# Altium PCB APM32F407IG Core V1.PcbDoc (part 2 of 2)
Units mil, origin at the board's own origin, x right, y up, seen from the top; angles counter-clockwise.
Board outline 2360 x 2950 mil, 4 copper layers (Top Layer, Signal, GND, Bottom Layer); 55 components, 152 nets, 502 pads, 608 vias.
Unrouted connection lines stored in the file: 294.
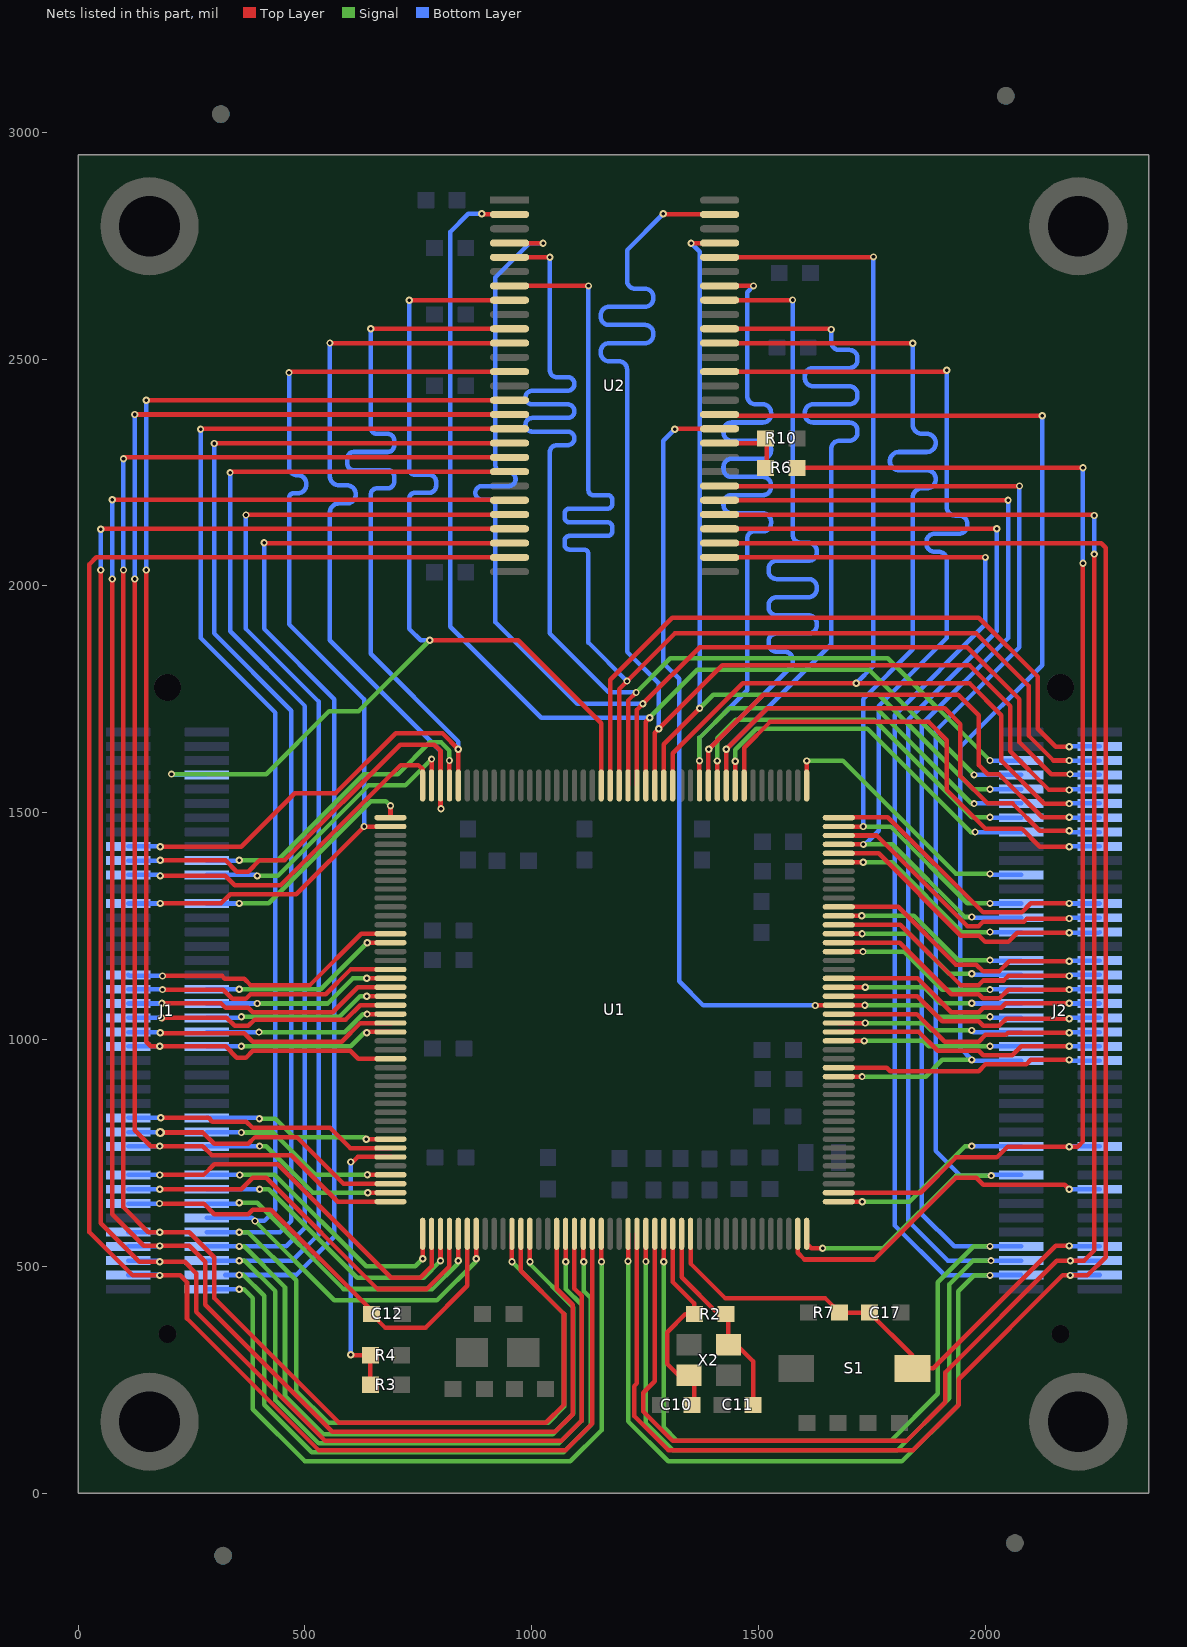
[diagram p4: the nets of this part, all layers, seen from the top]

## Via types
v1: diameter 16, hole 8, Top Layer to Bottom Layer, 452 vias
v2: diameter 24, hole 12, Top Layer to Bottom Layer, 149 vias
v3: diameter 20, hole 10, Top Layer to Bottom Layer, 7 vias

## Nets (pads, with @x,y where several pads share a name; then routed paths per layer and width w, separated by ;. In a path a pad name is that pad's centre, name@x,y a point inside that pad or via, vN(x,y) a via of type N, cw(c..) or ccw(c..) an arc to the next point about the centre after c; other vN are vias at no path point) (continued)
PD4_LCD_RD: J1.36 U1.146 | length 634.5
  Top Layer w10: v1(186.06,1140) 317.31,1140 323.31,1134 366,1134 380,1120 511.06,1120 624.21,1233.15 U1.146@688.58,1233.15
  Bottom Layer w10: J1.36@110.2,1142.31 112.5,1140 v1(186.06,1140)
PD5_LCD_WR: J1.37 U1.147 | length 447.7
  Top Layer w10: v1(637.6,1213.46) U1.147@688.58,1213.46
  Signal w10: v1(355,1110.81) 534.94,1110.81 v1(637.6,1213.46)
  Bottom Layer w10: J1.37@283.43,1110.81 v1(355,1110.81)
PD6_CTP_RST: J1.38 U1.150 | length 613.7
  Top Layer w10: v1(186.06,1110) 320,1110 340,1090 370,1090 380,1100 546.06,1100 600.47,1154.41 U1.150@688.58,1154.41
  Signal w10: v1@185.25,1110.81 v1(186.06,1110)
  Bottom Layer w10: J1.38@110.2,1110.81 v1@185.25,1110.81
PD7_CTP_SCL: J1.39 U1.151 | length 428.1
  Top Layer w10: v1(636.34,1134.72) U1.151@688.58,1134.72
  Signal w10: v1(395,1079.31) 550.38,1079.31 605.79,1134.72 v1(636.34,1134.72)
  Bottom Layer w10: J1.39@283.43,1079.31 v1(395,1079.31)
PD8_SMC_D13: J2.17 U1.96 | length 1069.2
  Top Layer w10: U1.96@1468.11,1559.92 1468.11,1643.11 1525,1700 1875,1700 1915,1660 1915,1550 2000,1465 2080,1465 2120,1425 v1(2185,1425)
  Bottom Layer w10: v1(2185,1425) 2185.77,1425.77 J2.17@2251.93,1425.77
PD9_SMC_D14: J2.16 U1.97 | length 822.4
  Top Layer w10: U1.97@1448.43,1559.92 v1(1448.43,1613.43)
  Signal w10: v1(1448.43,1613.43) 1448.43,1638.43 1495,1685 1740,1685 1967.73,1457.27 v1(1977.27,1457.27)
  Bottom Layer w10: v1(1977.27,1457.27) J2.16@2078.7,1457.27
PD10_SDR_D10: J2.15 U1.98 U2.45 | length 2874.1
  Top Layer w10: U2.45@1414.05,2566.64 v1@1660,2566.64 ; U1.98@1428.74,1559.92 v1(1428.74,1640) 1518.74,1730 1910,1730 1945,1695 1945,1580 2004.74,1520.26 2059.74,1520.26 2120,1460 v1(2184.53,1460)
  Bottom Layer w10: v1(1428.74,1640) 1660,1871.26 1660,2302 cw(c1678,2302) 1678,2320 1699.92,2320 ccw(c1699.92,2338) 1717.92,2338 1717.92,2342 ccw(c1699.92,2342) 1699.92,2360 1620.08,2360 cw(c1620.08,2378) 1602.08,2378 1602.08,2382 cw(c1620.08,2382) 1620.08,2400 1699.92,2400 ccw(c1699.92,2418) 1717.92,2418 1717.92,2422 ccw(c1699.92,2422) 1699.92,2440 1620.08,2440 cw(c1620.08,2458) 1602.08,2458 1602.08,2462 cw(c1620.08,2462) 1620.08,2480 1699.92,2480 ccw(c1699.92,2498) 1717.92,2498 1717.92,2502 ccw(c1699.92,2502) 1699.92,2520 1678,2520 cw(c1678,2538) 1660,2538 v1(1660,2565) ; v1(2184.53,1460) 2187.27,1457.27 J2.15@2251.93,1457.27
PD11_ETH_RESET: J2.14 U1.99 | length 880.3
  Top Layer w10: U1.99@1409.06,1559.92 v1(1409.06,1614.06)
  Signal w10: v1(1409.06,1614.06) 1409.06,1664.06 1450,1705 1755,1705 1970,1490 v1(2010,1490)
  Bottom Layer w10: v1(2010,1490) 2011.24,1488.76 J2.14@2078.7,1488.76
PD12_SDR_D11: J2.13 U1.100 U2.47 | length 2925
  Top Layer w10: U1.100@1389.37,1559.92 1389.37,1639.37 v1(1390,1640) 1510,1760 1940,1760 1985,1715 1985,1605 2005,1585 2030,1585 2125,1490 v1(2185,1490) ; U2.47@1414.05,2629.63 v1@1575,2629.63
  Bottom Layer w10: v1(1390,1640) 1575,1825 1575,1837 ccw(c1557,1837) 1557,1855 1539.93,1855 cw(c1539.93,1873) 1521.93,1873 1521.93,1877 cw(c1539.93,1877) 1539.93,1895 1610.06,1895 ccw(c1610.06,1913) 1628.06,1913 1628.06,1917 ccw(c1610.06,1917) 1610.06,1935 1539.94,1935 cw(c1539.94,1953) 1521.94,1953 1521.94,1957 cw(c1539.94,1957) 1539.94,1975 1610.06,1975 ccw(c1610.06,1993) 1628.06,1993 1628.06,1997 ccw(c1610.06,1997) 1610.06,2015 1539.94,2015 cw(c1539.94,2033) 1521.94,2033 1521.94,2037 cw(c1539.94,2037) 1539.94,2055 1610.06,2055 ccw(c1610.06,2073) 1628.06,2073 1628.06,2077 ccw(c1610.06,2077) 1610.06,2095 1593,2095 cw(c1593,2113) 1575,2113 v1(1575,2630) ; v1(2185,1490) 2186.24,1488.76 J2.13@2251.93,1488.76
PD13_SDR_D12: J2.12 U1.101 U2.48 | length 2709.7
  Top Layer w10: U1.101@1369.69,1559.92 v1(1369.69,1614.69) ; U2.48@1414.05,2661.13 v1(1488.87,2661.13)
  Signal w10: v1(1369.69,1614.69) 1369.69,1664.69 1435,1730 1760,1730 1970,1520 v1(1975,1520)
  Bottom Layer w10: v1(1369.69,1614.69) 1369.69,1664.69 1475,1770 1475,2105 cw(c1490,2105) 1490,2120 1509.39,2120 ccw(c1509.39,2138) 1527.39,2138 1527.39,2142 ccw(c1509.39,2142) 1509.39,2160 1440.61,2160 cw(c1440.61,2178) 1422.61,2178 1422.61,2182 cw(c1440.61,2182) 1440.61,2200 1509.39,2200 ccw(c1509.39,2218) 1527.39,2218 1527.39,2222 ccw(c1509.39,2222) 1509.39,2240 1440.61,2240 cw(c1440.61,2258) 1422.61,2258 1422.61,2262 cw(c1440.61,2262) 1440.61,2280 1509.39,2280 ccw(c1509.39,2298) 1527.39,2298 1527.39,2302 ccw(c1509.39,2302) 1509.39,2320 1440.61,2320 cw(c1440.61,2338) 1422.61,2338 1422.61,2342 cw(c1440.61,2342) 1440.61,2360 1509.39,2360 ccw(c1509.39,2378) 1527.39,2378 1527.39,2382 ccw(c1509.39,2382) 1509.39,2400 1493,2400 cw(c1493,2418) 1475,2418 1475,2647.25 v1(1488.87,2661.13) ; v1(1975,1520) 1975.26,1520.26 J2.12@2078.7,1520.26
PD14_SDR_D13: J2.11 U1.104 U2.50 | length 2541.6
  Top Layer w10: U1.104@1310.63,1559.92 1310.63,1630.63 1465,1785 v1(1715,1785) 1965,1785 2035,1715 2035,1615 2130,1520 v1(2185,1520) ; U2.50@1414.05,2724.12 1754.12,2724.12 v1(1753.24,2725)
  Bottom Layer w10: v1(1715,1785) 1753.24,1823.24 v1(1753.24,2725) ; v1(2185,1520) 2185.26,1520.26 J2.11@2251.93,1520.26
PD15_SDR_D14: J2.10 U1.105 U2.51 | length 2107.3
  Top Layer w10: U1.105@1290.94,1559.92 1290.94,1650.94 v1(1370,1730) ; v1(1351.23,2755) 1350.61,2755.61 U2.51@1414.05,2755.61
  Signal w10: v1(1370,1730) 1400,1760 1765,1760 1973.25,1551.75 v1(2010,1551.75)
  Bottom Layer w10: v1(1351.23,2755) 1370,2736.23 v1(1370,1730) ; v1(2010,1551.75) J2.10@2078.7,1551.75
PDR_ON: R3.1 R4.2 U1.171 | length 625.6
  Top Layer w10: v1(601.06,305) 602.06,304 R4.2@644.16,304 R3.1@644.16,239 ; v1(601.06,730) 605.04,730 616.06,741.02 U1.171@688.58,741.02
  Bottom Layer w10: v1(601.06,305) v1(601.06,730)
PE0: J1.55 U1.169 | length 424.9
  Top Layer w10: v1(635,780) 635.39,780.39 U1.169@688.58,780.39
  Signal w10: v1(399.69,825) 435,825 475,785 630,785 v1(635,780)
  Bottom Layer w10: J1.55@283.43,827.34 397.34,827.34 v1(399.69,825)
PE1: J1.56 U1.170 | length 606
  Top Layer w10: v1(182.34,827.34) 287.66,827.34 296,819 371,819 385,805 555.71,805 600,760.71 U1.170@688.58,760.71
  Bottom Layer w10: J1.56@110.2,827.34 v1(182.34,827.34)
PE2_CTP_INT: J1.63 U1.1 | length 621.4
  Top Layer w10: v1(759.45,516.61) U1.1@759.45,571.73
  Signal w10: v1(356.36,701.36) 433.64,701.36 635,500 742.83,500 v1(759.45,516.61)
  Bottom Layer w10: J1.63@283.43,701.36 v1(356.36,701.36)
PE3_LCD_RST: J1.64 U1.2 | length 864.4
  Top Layer w10: v1(179.7,701.36) 276.36,701.36 300,725 440,725 690,475 754.13,475 779.13,500 U1.2@779.13,571.73
  Bottom Layer w10: J1.64@110.2,701.36 v1(179.7,701.36)
PE4_DCMI_D4: J1.65 U1.3 | length 671.1
  Top Layer w10: v1(798.82,512.24) U1.3@798.82,571.73
  Signal w10: v1(400,670) 420,670 615,475 761.57,475 v1(798.82,512.24)
  Bottom Layer w10: J1.65@283.43,669.86 399.86,669.86 v1(400,670)
PE5_DCMI_D6: J1.66 U1.4 | length 913.6
  Top Layer w10: v1(180,669.86) 359.86,669.86 385,695 415,695 660,450 768.5,450 818.5,500 U1.4@818.5,571.73
  Bottom Layer w10: J1.66@110.2,669.86 v1(180,669.86) v1@180.93,669.86
PE6_DCMI_D7: J1.67 U1.5 | length 722.4
  Top Layer w10: v1(838.19,512.13) U1.5@838.19,571.73
  Signal w10: v1(355,640) 395,640 585,450 781.06,450 838.19,507.13 v1(838.19,512.13)
  Bottom Layer w10: J1.67@283.43,638.37 353.37,638.37 v1(355,640)
PE7_SMC_D4: J2.41 U1.68 | length 609.6
  Top Layer w10: U1.68@1676.77,1095.35 1849.65,1095.35 1905,1040 1985,1040 1995,1030 2030,1030 2045.63,1045.63 v1(2185,1045.63)
  Bottom Layer w10: v1(2185,1045.63) 2187.18,1047.82 J2.41@2251.93,1047.82
PE8_SMC_D5: J2.40 U1.69 | length 416.7
  Top Layer w10: U1.69@1676.77,1115.04 v1(1734.96,1115.04)
  Signal w10: v1(1734.96,1115.04) 1864.96,1115.04 1900,1080 v1(1970,1080)
  Bottom Layer w10: v1(1970,1080) 1970.69,1079.31 J2.40@2078.7,1079.31
PE9_SMC_D6: J2.39 U1.70 | length 614.7
  Top Layer w10: U1.70@1676.77,1134.72 1850.28,1134.72 1925,1060 1985,1060 1995,1070 2035,1070 2045,1080 v1(2185,1080)
  Bottom Layer w10: v1(2185,1080) 2185.69,1079.31 J2.39@2251.93,1079.31
PE10_SMC_D7: J2.38 U1.73 | length 437
  Top Layer w10: U1.73@1676.77,1193.78 v1(1730,1193.78)
  Signal w10: v1(1730,1193.78) 1821.22,1193.78 1905,1110 v1(2010,1110)
  Bottom Layer w10: v1(2010,1110) 2010.81,1110.81 J2.38@2078.7,1110.81
PE11_SMC_D8: J2.37 U1.74 | length 634.1
  Top Layer w10: U1.74@1676.77,1213.46 1811.54,1213.46 1925,1100 1985,1100 1994,1091 2031,1091 2050,1110 v1(2185,1110)
  Bottom Layer w10: v1(2185,1110) 2185.81,1110.81 J2.37@2251.93,1110.81
PE12_SMC_D9: J2.36 U1.75 | length 439.6
  Top Layer w10: U1.75@1676.77,1233.15 v1(1728.15,1233.15)
  Signal w10: v1(1728.15,1233.15) 1831.85,1233.15 1920,1145 v1(1970,1145)
  Bottom Layer w10: v1(1970,1145) 1972.7,1142.3 J2.36@2078.7,1142.3
PE13_SMC_D10: J2.35 U1.76 | length 639.4
  Top Layer w10: U1.76@1676.77,1252.83 1812.17,1252.83 1945,1120 1985,1120 1995,1130 2040,1130 2050,1140 v1(2185,1140)
  Bottom Layer w10: v1(2185,1140) 2187.3,1142.3 J2.35@2251.93,1142.3
PE14_SMC_D11: J2.34 U1.77 | length 442.8
  Top Layer w10: U1.77@1676.77,1272.52 v1(1727.48,1272.52)
  Signal w10: v1(1727.48,1272.52) 1842.48,1272.52 1940,1175 v1(2010,1175)
  Bottom Layer w10: v1(2010,1175) 2011.2,1173.8 J2.34@2078.7,1173.8
PE15_SMC_D12: J2.33 U1.78 | length 643.9
  Top Layer w10: U1.78@1676.77,1292.2 1807.8,1292.2 1935,1165 1980,1165 1995,1150 2030,1150 2052.6,1172.6 v1(2185,1172.6)
  Bottom Layer w10: v1(2185,1172.6) 2186.2,1173.8 J2.33@2251.93,1173.8
PF0_SDR_A10: J1.74 U1.16 U2.22 | length 4218.3
  Top Layer w10: v1(75,2015) 75,1825 75,615 145,545 v1(180,545) 245,545 280,510 280,415 560,135 1051.06,135 1090,173.94 1090,415 1054.72,450.28 U1.16@1054.72,571.73 ; v1(75,2190) 949.74,2190 U2.22@951.05,2188.68
  Bottom Layer w10: v1(75,2015) v1(75,2190) ; J1.74@110.2,543.88 v1@178.88,543.88
PF1_SDR_A0: J1.75 U1.17 U2.23 | length 4013.2
  Top Layer w10: v1@370,2157.19 U2.23@951.05,2157.19 ; U1.17@1074.41,571.73 1074.41,510.59 v1(1075,510)
  Signal w10: v1(355,512.38) 367.62,512.38 435,445 435,205 530,110 1060,110 1110,160 1110,415 1075,450 v1(1075,510)
  Bottom Layer w10: J1.75@283.43,512.38 v1(355,512.38) 472.38,512.38 530,570 530,1745 370,1905 v1(370,2156)
PF2_SDR_A1: J1.76 U1.18 U2.24 | length 4243.4
  Top Layer w10: v1(50,2035) 50,1840 50,595 135,510 v1(180,510) 235,510 260,485 260,400 545,115 1065,115 1110,160 1110,435 1094.09,450.91 U1.18@1094.09,571.73 ; v1@50.69,2125.69 U2.24@951.05,2125.69
  Bottom Layer w10: v1(50,2035) v1(50,2125) ; J1.76@110.2,512.38 v1@177.62,512.38
PF3_SDR_A2: J1.77 U1.19 U2.25 | length 3941.8
  Top Layer w10: v1@410,2094.2 U2.25@951.05,2094.2 ; U1.19@1113.78,571.73 1113.78,510.69 v1(1114.46,510)
  Signal w10: v1(355,480.89) 364.11,480.89 410,435 410,195 515,90 1070,90 1130,150 1130,430 1114.46,445.54 v1(1114.46,510)
  Bottom Layer w10: J1.77@324.11,480.89 v1(355,480.89) 480.89,480.89 565,565 565,1750 410,1905 v1(410,2095)
PF4_SDR_A3: J1.78 U1.20 U2.26 | length 4271.8
  Top Layer w10: U2.26@951.05,2062.7 40,2062.7 25,2047.7 25,1825 25,575 120,480 v1(180,480) 225,480 240,465 240,385 530,95 1075,95 1133.46,153.46 U1.20@1133.46,571.73
  Bottom Layer w10: J1.78@110.2,480.89 179.11,480.89 v1(180,480)
PF5_SPI_CS: J1.79 U1.21 | length 1632.8
  Top Layer w10: U1.21@1153.15,571.73 1153.15,510.69 v1(1153.83,510)
  Signal w10: v1(355,449.39) 365.61,449.39 385,430 385,185 500,70 1085,70 1153.83,138.83 v1(1153.83,510)
  Bottom Layer w10: J1.79@283.43,449.39 v1(355,449.39)
PF6_SDR_A4: J2.78 U1.24 U2.29 | length 4030.1
  Top Layer w10: v1(1212.2,511.14) U1.24@1212.2,571.73 ; U2.29@1414.05,2062.7 v1(2000,2062.7)
  Signal w10: v1(1212.2,511.14) 1212.2,158.86 1301.06,70 1816.06,70 1940,193.94 1940,445 1975,480 v1(2010,480)
  Bottom Layer w10: v1(2000,2062.7) 2000,1915 1800,1715 1800,590 1910,480 v1(2010,480) ; v1@2010,480.89 J2.78@2078.7,480.89
PF7_SDR_A5: J2.77 U1.25 U2.30 | length 4169.6
  Top Layer w10: U1.25@1231.89,571.73 1231.89,241.89 1226.06,236.06 1226.06,170 1301.06,95 1841.06,95 1941.06,195 1941.06,251.06 2170,480 v1(2186.77,480) 2225,480 2265,520 2265,1830 2265,2084.2 2255,2094.2 U2.30@1414.05,2094.2
  Bottom Layer w10: v1(2186.77,480) 2185.89,480.89 J2.77@2251.93,480.89
PF8_SDR_A6: J2.76 U1.26 U2.31 | length 4025.3
  Top Layer w10: v1(1251.57,510.51) U1.26@1251.57,571.73 ; U2.31@1414.05,2125.69 v1(2025,2125.69)
  Signal w10: v1(1251.57,510.51) 1251.57,154.49 1311.06,95 1806.06,95 1920,208.94 1920,460 1972.62,512.62 v1(2012.38,512.62)
  Bottom Layer w10: v1(2025,2125.69) 2025,1900 1830,1705 1830,600 1917.38,512.62 v1(2012.38,512.62) 2012.38,512.38 J2.76@2078.7,512.38
PF9_SDR_A7: J2.75 U1.27 U2.32 | length 4146.2
  Top Layer w10: U1.27@1271.26,571.73 1271.26,246.26 1246.06,221.06 1246.06,180 1311.06,115 1826.06,115 1911.06,200 1911.06,266.06 2157.38,512.38 v1(2187.38,512.38) 2217.38,512.38 2240,535 2240,1850 v1(2240,2070) ; U2.32@1414.05,2157.19 v1@2240,2157.19
  Bottom Layer w10: v1(2187.38,512.38) J2.75@2251.93,512.38 ; v1(2240,2070) v1(2240,2155)
PF10_SDR_A8: J2.74 U1.28 U2.33 | length 4016.4
  Top Layer w10: v1(1290.94,510.12) U1.28@1290.94,571.73 ; U2.33@1414.05,2188.68 v1(2050,2188.68)
  Signal w10: v1(1290.94,510.12) 1290.94,145.12 1321.06,115 1791.06,115 1895,218.94 1895,465 1973.88,543.88 v1(2010,543.88)
  Bottom Layer w10: v1(2050,2188.68) 2050,1885 1860,1695 1860,615 1931.12,543.88 v1(2010,543.88) J2.74@2078.7,543.88
PF11_SDR_UDQM: J2.48 U1.59 U2.39 | length 2634.8
  Top Layer w10: U2.39@1414.05,2377.66 1416.71,2375 v1(2125,2375) ; U1.59@1676.77,918.19 v1(1728.19,918.19)
  Signal w10: v1(1728.19,918.19) 1868.19,918.19 1905,955 v1(1970,955)
  Bottom Layer w10: J2.48@2078.7,953.33 1971.67,953.33 v1(1970,955) 1945,980 1945,1645 2125,1825 v1(2125,2375)
PF12_KEY3: J2.47 U1.60 | length 589.5
  Top Layer w10: U1.60@1676.77,937.87 1782.13,937.87 1790,930 1985,930 2000,945 2090,945 2100,955 v1(2185,955)
  Bottom Layer w10: v1(2185,955) 2186.67,953.33 J2.47@2251.93,953.33
PF13_CAMER_RST: J2.46 U1.63 | length 406.9
  Top Layer w10: U1.63@1676.77,996.93 v1(1733.07,996.93)
  Signal w10: v1(1733.07,996.93) 1863.07,996.93 1875,985 v1(2010,985)
  Bottom Layer w10: v1(2010,985) 2010.18,984.82 J2.46@2078.7,984.82
PF14_LCD_BK: J2.45 U1.64 | length 604.9
  Top Layer w10: U1.64@1676.77,1016.61 1853.39,1016.61 1895,975 1985,975 1995,965 2058.88,965 2078.88,985 v1(2185,985)
  Bottom Layer w10: v1(2185,985) 2185.18,984.82 J2.45@2251.93,984.82
PF15_485_EN: J2.44 U1.65 | length 410.2
  Top Layer w10: U1.65@1676.77,1036.3 v1(1735,1036.3)
  Signal w10: v1(1735,1036.3) 1863.7,1036.3 1880,1020 v1(1970,1020)
  Bottom Layer w10: v1(1970,1020) 1973.68,1016.32 J2.44@2078.7,1016.32
PG0: J2.43 U1.66 | length 609.2
  Top Layer w10: U1.66@1676.77,1055.98 1849.02,1055.98 1910,995 1985,995 2000,1010 2045,1010 2050,1015 v1(2185,1015)
  Bottom Layer w10: v1(2185,1015) 2186.32,1016.32 J2.43@2251.93,1016.32
PG1_SDR_CLK: J2.42 U1.67 U2.38 | length 2128.8
  Top Layer w10: v1(1315,2345) 1316.16,2346.16 U2.38@1414.05,2346.16 ; v1(1625,1075) 1625.67,1075.67 U1.67@1676.77,1075.67 v1(1734.33,1075.67)
  Signal w10: v1(1734.33,1075.67) 1869.33,1075.67 1895,1050 v1(2010,1050)
  Bottom Layer w10: v1(1315,2345) 1290,2320 1290,1830 1325,1795 1325,1128.13 1378.13,1075 v1(1625,1075) ; v1(2010,1050) 2012.18,1047.82 J2.42@2078.7,1047.82
PG2_SDR_D15: J2.9 U1.106 U2.53 | length 3039.7
  Top Layer w10: U1.106@1271.26,1559.92 1271.26,1676.26 v1(1280,1685) 1420,1825 1965,1825 2055,1735 2055,1635 2140,1550 v1(2185,1550) ; v1(1290,2820) 1291.39,2818.61 U2.53@1414.05,2818.61
  Bottom Layer w10: v1(1280,1685) 1280,1785 1210,1855 1210,2477 ccw(c1192,2477) 1192,2495 1170.08,2495 cw(c1170.08,2513) 1152.08,2513 1152.08,2517 cw(c1170.08,2517) 1170.08,2535 1249.92,2535 ccw(c1249.92,2553) 1267.92,2553 1267.92,2557 ccw(c1249.92,2557) 1249.92,2575 1170.08,2575 cw(c1170.08,2593) 1152.08,2593 1152.08,2597 cw(c1170.08,2597) 1170.08,2615 1249.92,2615 ccw(c1249.92,2633) 1267.92,2633 1267.92,2637 ccw(c1249.92,2637) 1249.92,2655 1228,2655 cw(c1228,2673) 1210,2673 1210,2740 v1(1290,2820) ; v1(2185,1550) 2186.75,1551.75 J2.9@2251.93,1551.75
PG3_SDR_D0: J2.8 U1.107 U2.2 | length 2653.2
  Top Layer w10: v1(890,2820) 891.39,2818.61 U2.2@951.05,2818.61 ; U1.107@1251.57,1559.92 1251.57,1700.51 v1(1260,1708.94)
  Signal w10: v1(1260,1708.94) 1260,1710 1365,1815 1743.25,1815 v1(1975,1583.25)
  Bottom Layer w10: v1(890,2820) 860,2820 820,2780 820,1910 1021.06,1708.94 v1(1260,1708.94) ; v1(1975,1583.25) J2.8@2078.7,1583.25
PG4_SDR_D1: J2.7 U1.108 U2.4 | length 2925
  Top Layer w10: U2.4@951.05,2755.61 1024.39,2755.61 v1(1025,2755) ; U1.108@1231.89,1559.92 1231.89,1726.89 v1(1245,1740) 1370,1865 1960,1865 2075,1750 2075,1655 2145,1585 v1(2186.5,1585)
  Bottom Layer w10: v1(1025,2755) 995,2755 920,2680 920,2265 ccw(c935,2265) 935,2250 949.32,2250 cw(c949.32,2235) 964.32,2235 cw(c949.32,2235) 949.32,2220 890.68,2220 ccw(c890.68,2205) 875.68,2205 ccw(c890.68,2205) 890.68,2190 905,2190 cw(c905,2175) 920,2175 920,1920 1100,1740 v1(1245,1740) ; v1(2186.5,1585) 2188.25,1583.25 J2.7@2251.93,1583.25
PG5_SDR_D2: J2.6 U1.109 U2.5 | length 2809.6
  Top Layer w10: U2.5@951.05,2724.12 v1(1040,2724.12) ; U1.109@1212.2,1559.92 1212.2,1747.2 v1(1230,1765)
  Signal w10: v1(1230,1765) 1305,1840 1785,1840 v1(2010,1615)
  Bottom Layer w10: v1(1040,2724.12) 1040,2475 ccw(c1055,2475) 1055,2460 1078.94,2460 cw(c1078.94,2445) 1093.94,2445 cw(c1078.94,2445) 1078.94,2430 1001.06,2430 ccw(c1001.06,2415) 986.06,2415 ccw(c1001.06,2415) 1001.06,2400 1078.94,2400 cw(c1078.94,2385) 1093.94,2385 cw(c1078.94,2385) 1078.94,2370 1001.06,2370 ccw(c1001.06,2355) 986.06,2355 ccw(c1001.06,2355) 1001.06,2340 1078.94,2340 cw(c1078.94,2325) 1093.94,2325 cw(c1078.94,2325) 1078.94,2310 1055,2310 ccw(c1055,2295) 1040,2295 1040,1895 1170,1765 v1(1230,1765) ; v1(2010,1615) 2010.25,1614.75 J2.6@2078.7,1614.75
PG6_SDR_D3: J2.5 U1.110 U2.7 | length 2959.2
  Top Layer w10: U2.7@951.05,2661.13 v1(1125,2661.13) ; U1.110@1192.52,1559.92 1192.52,1772.52 v1(1210,1790) 1315,1895 1980,1895 2095,1780 2095,1670 2150,1615 v1(2185,1615)
  Bottom Layer w10: v1(1125,2661.13) 1125,2210.5 ccw(c1135.5,2210.5) 1135.5,2200 1167.09,2200 cw(c1167.09,2189.5) 1177.59,2189.5 1177.59,2180.5 cw(c1167.09,2180.5) 1167.09,2170 1082.91,2170 ccw(c1082.91,2159.5) 1072.41,2159.5 1072.41,2150.5 ccw(c1082.91,2150.5) 1082.91,2140 1167.09,2140 cw(c1167.09,2129.5) 1177.59,2129.5 1177.59,2120.5 cw(c1167.09,2120.5) 1167.09,2110 1082.91,2110 ccw(c1082.91,2099.5) 1072.41,2099.5 1072.41,2090.5 ccw(c1082.91,2090.5) 1082.91,2080 1114.5,2080 cw(c1114.5,2069.5) 1125,2069.5 1125,1875 v1(1210,1790) ; v1(2185,1615) 2185.25,1614.75 J2.5@2251.93,1614.75
PG7_BUZ: J2.3 U1.111 | length 1554.8
  Top Layer w10: U1.111@1172.83,1559.92 1172.83,1792.83 1310,1930 1985,1930 2115,1800 2115,1685 2155,1645 v1(2185,1645)
  Bottom Layer w10: v1(2185,1645) 2186.24,1646.24 J2.3@2251.93,1646.24
PG8_SDR_D4: J1.7 U1.112 U2.8 | length 2455.9
  Top Layer w10: v1(730,2629.63) U2.8@951.05,2629.63 ; v1(775,1880) 970,1880 1153.15,1696.85 U1.112@1153.15,1559.92
  Signal w10: v1(206,1585) 415,1585 553.94,1723.94 618.94,1723.94 v1(775,1880)
  Bottom Layer w10: v1(206,1585) 207.75,1583.25 J1.7@283.43,1583.25 ; v1(730,2629.63) 730,2257 ccw(c742,2257) 742,2245 773.63,2245 cw(c773.63,2229.58) 789.06,2229.58 789.06,2220.42 cw(c773.63,2220.42) 773.63,2205 742,2205 ccw(c742,2193) 730,2193 730,1905 755,1880 v1(775,1880)
PG9_LCD_RS: J1.40 U1.152 | length 611.1
  Top Layer w10: v1(184.69,1080) 315,1080 325,1070 375,1070 385,1060 561.06,1060 616.1,1115.04 U1.152@688.58,1115.04
  Signal w10: v1(184.69,1080) v1@185.38,1079.31
  Bottom Layer w10: J1.40@110.2,1079.31 v1@185.38,1079.31
PG10_LCD_CS: J1.41 U1.153 | length 424.8
  Top Layer w10: v1(636.42,1095.35) U1.153@688.58,1095.35
  Signal w10: v1(360,1050) 576.06,1050 621.42,1095.35 v1(636.42,1095.35)
  Bottom Layer w10: J1.41@283.43,1047.82 357.82,1047.82 v1(360,1050)
PG11_RMII_TX_EN: J1.42 U1.154 | length 608.7
  Top Layer w10: v1@186.7,1045 v1(183.88,1047.82) 327.18,1047.82 345,1030 375,1030 389,1044 590.06,1044 621.73,1075.67 U1.154@688.58,1075.67
  Bottom Layer w10: J1.42@110.2,1047.82 v1(183.88,1047.82)
PG12: J1.43 U1.155 | length 421.6
  Top Layer w10: v1(637.05,1055.98) U1.155@688.58,1055.98
  Signal w10: v1(398.68,1016.32) 587.38,1016.32 627.05,1055.98 v1(637.05,1055.98)
  Bottom Layer w10: J1.43@283.43,1016.32 v1(398.68,1016.32)
PG13_RMII_TXD0: J1.44 U1.156 | length 604.3
  Top Layer w10: v1(181.06,1015) 182.06,1014 366,1014 385,995 581.06,995 622.36,1036.3 U1.156@688.58,1036.3
  Signal w10: v1@179.74,1016.32 v1(181.06,1015)
  Bottom Layer w10: J1.44@110.2,1016.32 v1@179.74,1016.32
PG14_RMII_TXD1: J1.45 U1.157 | length 418.3
  Top Layer w10: v1(636.06,1015) 637.68,1016.61 U1.157@688.58,1016.61
  Signal w10: v1(360,985) 601.06,985 631.06,1015 v1(636.06,1015)
  Bottom Layer w10: J1.45@283.43,984.82 359.82,984.82 v1(360,985)
PG15_SDR_LDQM: J1.46 U1.160 U2.15 | length 2851.4
  Top Layer w10: v1(150,2035) 150,1840 150,995 160.18,984.82 v1(179.82,984.82) 325.18,984.82 350,960 370,960 385,975 600,975 617.44,957.56 U1.160@688.58,957.56 ; v1(150,2409.16) U2.15@951.05,2409.16
  Bottom Layer w10: J1.46@110.2,984.82 v1(179.82,984.82) ; v1(150,2035) v1(150,2409.16)
PH0: C10.1 R2.2 U1.29 X2.3 | length 478.3
  Top Layer w10: U1.29@1310.63,571.73 1310.63,465.43 1357.68,418.39 1357.68,396.23 R2.2@1359.16,394.75 1338.6,394.75 1298.6,354.75 1298.6,284.75 1323.6,259.75 X2.3@1346.99,259.75 1358.6,248.14 C10.1@1358.6,189.2
PH1: C11.1 R2.1 U1.30 X2.1 | length 462.7
  Top Layer w10: U1.30@1330.32,571.73 1330.32,475.75 1411.31,394.75 R2.1@1428.05,394.75 1433.6,389.2 X2.1@1433.6,326.68 1451.67,326.68 1488.05,290.3 C11.1@1488.05,194.75
PH2: J2.65 U1.43 | length 798.7
  Top Layer w10: U1.43@1586.22,571.73 1586.22,529.84 1601.06,515 1755,515 1935,695 1980,695 1995,680 2175,680 v1(2185,670)
  Bottom Layer w10: v1(2185,670) 2185.14,669.86 J2.65@2251.93,669.86
PH3_SDR_A9: J2.64 U1.44 U2.34 | length 2916.3
  Top Layer w10: U2.34@1414.05,2220.18 1414.23,2220 v1(2075,2220) ; U1.44@1605.91,571.73 1605.91,550.16 1616.06,540 v1(1641.06,540)
  Signal w10: v1(1641.06,540) 1775,540 1935,700 v1(2012.72,700)
  Bottom Layer w10: v1(2075,2220) 2075,1865 1890,1680 1890,755 1945,700 v1(2012.72,700) 2011.36,701.36 J2.64@2078.7,701.36
PH4: J2.60 U1.45 | length 452.9
  Top Layer w10: U1.45@1676.77,642.6 v1(1728.46,642.6)
  Signal w10: v1(1728.46,642.6) 1832.6,642.6 1955,765 v1(1970,765)
  Bottom Layer w10: v1(1970,765) 1970.65,764.35 J2.60@2078.7,764.35
PH5_SDR_CKE: J2.59 R6.2 U1.46 | length 2767.7
  Top Layer w10: R6.2@1584.45,2260 v1(2215,2260) ; U1.46@1676.77,662.28 1857.28,662.28 1935,740 2025,740 2048.7,763.7 v1(2185,763.7) 2203.7,763.7 2215,775 2215,1830 v1(2215,2050)
  Bottom Layer w10: v1(2185,763.7) 2185.65,764.35 J2.59@2251.93,764.35 ; v1(2215,2050) v1(2215,2260)
PH6: J2.30 U1.83 | length 465.7
  Top Layer w10: U1.83@1676.77,1390.63 v1(1730.43,1390.63)
  Signal w10: v1(1730.43,1390.63) 1794.37,1390.63 1948.21,1236.79 v1(2010,1236.79)
  Bottom Layer w10: v1(2010,1236.79) J2.30@2078.7,1236.79
PH7: J2.29 U1.84 | length 665.1
  Top Layer w10: U1.84@1676.77,1410.32 1764.68,1410.32 1946,1229 1986,1229 2000,1215 2050,1215 2070,1235 v1(2185,1235)
  Bottom Layer w10: v1(2185,1235) 2250.14,1235 J2.29@2251.93,1236.79
PH8_SDR_D8: J2.28 U1.85 U2.42 | length 2228.4
  Top Layer w10: U2.42@1414.05,2472.15 1912.15,2472.15 v1(1915,2475) ; U1.85@1676.77,1430 v1(1731.06,1430)
  Signal w10: v1(1731.06,1430) 1795,1430 1955,1270 v1(1970,1270)
  Bottom Layer w10: v1(1731.06,1430) 1735,1430 1765,1460 1765,1735 1915,1885 1915,2057 ccw(c1897,2057) 1897,2075 1887.96,2075 cw(c1887.96,2093) 1869.96,2093 1869.96,2097 cw(c1887.96,2097) 1887.96,2115 1942.04,2115 ccw(c1942.04,2133) 1960.04,2133 1960.04,2137 ccw(c1942.04,2137) 1942.04,2155 1933,2155 cw(c1933,2173) 1915,2173 v1(1915,2475) ; v1(1970,1270) 1971.71,1268.29 J2.28@2078.7,1268.29
PH9: J2.27 U1.86 | length 667
  Top Layer w10: U1.86@1676.77,1449.69 1760.31,1449.69 1960,1250 1985,1250 1995,1260 2085,1260 2091.58,1266.58 v1(2185,1266.58)
  Bottom Layer w10: v1@2185,1265 v1(2185,1266.58) 2186.71,1268.29 J2.27@2251.93,1268.29
PH10_SDR_D9: J2.26 U1.87 U2.44 | length 2244
  Top Layer w10: U2.44@1414.05,2535.14 1839.86,2535.14 v1(1840,2535) ; U1.87@1676.77,1469.37 v1(1730.43,1469.37)
  Signal w10: v1(1730.43,1469.37) 1790.63,1469.37 1960,1300 v1(2010,1300)
  Bottom Layer w10: v1(1730.43,1469.37) 1730.43,1750.43 1840,1860 1840,2195 cw(c1860,2195) 1860,2215 1870.55,2215 ccw(c1870.55,2235) 1890.55,2235 ccw(c1870.55,2235) 1870.55,2255 1809.39,2255 cw(c1809.39,2275) 1789.39,2275 cw(c1809.39,2275) 1809.39,2295 1870.55,2295 ccw(c1870.55,2315) 1890.55,2315 ccw(c1870.55,2315) 1870.55,2335 1860,2335 cw(c1860,2355) 1840,2355 v1(1840,2535) ; v1(2010,1300) 2010.21,1299.79 J2.26@2078.7,1299.79
PH11: J2.25 U1.88 | length 670.9
  Top Layer w10: U1.88@1676.77,1489.06 1677.72,1490 1785,1490 1995,1280 2080,1280 2100,1300 v1(2185,1300)
  Bottom Layer w10: v1(2185,1300) 2185.21,1299.79 J2.25@2251.93,1299.79
PH12: J2.22 U1.89 | length 631.1
  Top Layer w10: U1.89@1605.91,1559.92 v1(1605.91,1614.09)
  Signal w10: v1(1605.91,1614.09) 1685.91,1614.09 1935,1365 v1(2010,1365)
  Bottom Layer w10: v1(2010,1365) 2012.22,1362.78 J2.22@2078.7,1362.78
PH13_SDR_D5: J1.18 U1.128 U2.10 | length 2500.4
  Top Layer w10: v1(181.06,1425) 360,1425 477.5,1542.5 567.5,1542.5 700,1675 803.19,1675 v1(838.19,1640) U1.128@838.19,1559.92 ; v1(645,2566.64) U2.10@951.05,2566.64
  Signal w10: v1@180.29,1425.77 v1(181.06,1425)
  Bottom Layer w10: J1.18@110.2,1425.77 v1@180.29,1425.77 ; v1(645,2566.64) 645,2349 ccw(c659,2349) 659,2335 682.55,2335 cw(c682.55,2321) 696.55,2321 696.55,2309 cw(c682.55,2309) 682.55,2295 607.45,2295 ccw(c607.45,2281) 593.45,2281 593.45,2269 ccw(c607.45,2269) 607.45,2255 682.55,2255 cw(c682.55,2241) 696.55,2241 696.55,2229 cw(c682.55,2229) 682.55,2215 659,2215 ccw(c659,2201) 645,2201 645,1850 838.19,1656.81 v1(838.19,1640)
PH14: J1.19 U1.129 | length 727.3
  Top Layer w10: U1.129@818.5,1559.92 v1(818.5,1615)
  Signal w10: v1(355,1395) 440,1395 630,1585 705,1585 775,1655 800,1655 818.5,1636.5 v1(818.5,1615)
  Bottom Layer w10: J1.19@283.43,1394.27 354.27,1394.27 v1(355,1395)
PH15_SDR_D6: J1.20 U1.130 U2.11 | length 2552.9
  Top Layer w10: v1(181.06,1395) 325,1395 350,1370 375,1370 400,1395 455,1395 710,1650 785,1650 798.82,1636.18 U1.130@798.82,1559.92 798.82,1509.92 v1(800,1508.74) ; v1(555,2535.14) U2.11@951.05,2535.14
  Signal w10: v1@180.34,1394.27 v1(181.06,1395)
  Bottom Layer w10: J1.20@110.2,1394.27 v1@180.34,1394.27 ; v1(555,2535.14) 555,2241.6 ccw(c575,2241.6) 575,2221.6 592.18,2221.6 cw(c592.18,2201.6) 612.18,2201.6 cw(c592.18,2201.6) 592.18,2181.6 575,2181.6 ccw(c575,2161.6) 555,2161.6 555,1880 799.5,1635.5 799.5,1509.24 v1(800,1508.74)
PI0: J1.21 U1.131 | length 661.4
  Top Layer w10: U1.131@779.13,1559.92 v1(779.13,1618.07)
  Signal w10: v1(395,1360.55) 440.56,1360.55 640,1560 721.06,1560 v1(779.13,1618.07)
  Bottom Layer w10: J1.21@283.43,1362.78 392.78,1362.78 v1(395,1360.55)
PI1: J1.22 U1.132 | length 812.4
  Top Layer w10: v1(181.06,1360.55) 324.45,1360.55 345,1340 446.06,1340 711.06,1605 750,1605 759.45,1595.55 U1.132@759.45,1559.92
  Signal w10: v1(181.06,1360.55) v1@183.29,1362.78
  Bottom Layer w10: J1.22@110.2,1362.78 v1@183.29,1362.78
PI2: J1.25 U1.133 | length 528.5
  Top Layer w10: U1.133@688.58,1489.06 v1(688.58,1515)
  Signal w10: v1(355,1300) 420,1300 645,1525 678.58,1525 v1(688.58,1515)
  Bottom Layer w10: J1.25@283.43,1299.79 354.79,1299.79 v1(355,1300)
PI3_SDR_D7: J1.26 U1.134 U2.13 | length 2252.7
  Top Layer w10: v1(181.06,1300) 315,1300 335,1320 481.06,1320 v1(630.43,1469.37) U1.134@688.58,1469.37 ; v1(465,2470) 467.15,2472.15 U2.13@951.05,2472.15
  Signal w10: v1@180.85,1299.79 v1(181.06,1300)
  Bottom Layer w10: J1.26@110.2,1299.79 v1@180.85,1299.79 ; v1(465,2470) 465,2262 ccw(c483,2262) 483,2244 484.63,2244 cw(c484.63,2226) 502.63,2226 502.63,2222 cw(c484.63,2222) 484.63,2204 474.6,2204 ccw(c474.6,2194.4) 465,2194.4 465,1915 630.43,1749.57 v1(630.43,1469.37)
PI4: J1.57 U1.173 | length 444.2
  Top Layer w10: v1(637.72,701.65) U1.173@688.58,701.65
  Signal w10: v1(360,795) 430,795 523.35,701.65 v1(637.72,701.65)
  Bottom Layer w10: J1.57@283.43,795.85 359.15,795.85 v1(360,795)
PI5: J1.58 U1.174 | length 638
  Top Layer w10: v3(181.06,795) 275,795 300,770 375,770 390,785 481.97,785 585,681.97 U1.174@688.58,681.97
  Signal w10: v3@180.21,795.85 v3(181.06,795)
  Bottom Layer w10: J1.58@110.2,795.85 v3@180.21,795.85
PI6: J1.59 U1.175 | length 448
  Top Layer w10: v1(638.35,662.28) U1.175@688.58,662.28
  Signal w10: v1(400,765) 415,765 517.72,662.28 v1(638.35,662.28)
  Bottom Layer w10: J1.59@283.43,764.35 399.35,764.35 v1(400,765)
PI7_SDR_NWE: J1.60 U1.176 U2.16 | length 3102.6
  Top Layer w10: v1(125,2015) 125,1825 125,800 160,765 v1(180,765) 275,765 295,745 470,745 572.4,642.6 U1.176@688.58,642.6 ; v1(125,2377.66) U2.16@951.05,2377.66
  Bottom Layer w10: J1.60@110.2,764.35 179.35,764.35 v1(180,765) ; v1(125,2015) v1(125,2377.66)
PI8_SDR_NCAS: J1.69 U1.7 U2.17 | length 3290.8
  Top Layer w10: v1(270,2345) 271.16,2346.16 U2.17@951.05,2346.16 ; v1(877.56,516.5) U1.7@877.56,571.73
  Signal w10: v1(390,600) 565,425 791.06,425 877.56,511.5 v1(877.56,516.5)
  Bottom Layer w10: v1(270,2345) 270,1885 435,1720 435,625 410,600 v1(390,600) 383.13,606.87 J1.69@283.43,606.87
PI9_SDR_NRAS: J1.71 U1.11 U2.18 | length 4109.7
  Top Layer w10: v1(300,2313.8) 300.87,2314.67 U2.18@951.05,2314.67 ; v1(956.3,510.24) U1.11@956.3,571.73
  Signal w10: v1(355,575) 355.38,575.38 374.62,575.38 481.06,468.94 481.06,225 551.06,155 1036.06,155 1071.06,190 1071.06,395 956.3,509.76 v1(956.3,510.24)
  Bottom Layer w10: J1.71@283.43,575.38 283.8,575 v1(355,575) 445,575 470,600 470,1725 300,1895 v1(300,2313.8)
PI10_SDR_NCS: J1.72 U1.12 U2.19 | length 4225.5
  Top Layer w10: v1(100,2035) 100,1840 100,630 155,575 v1(180,575) 245,575 300,520 300,430 575,155 1031.06,155 1071.06,195 1071.06,395 975.98,490.08 U1.12@975.98,571.73 ; v1(100,2280) 103.17,2283.17 U2.19@951.05,2283.17
  Bottom Layer w10: v1(100,2035) v1(100,2280) ; J1.72@110.2,575.38 179.62,575.38 v1(180,575)
PI11_SDR_BA: J1.73 U1.13 U2.20 | length 4085
  Top Layer w10: v1@335,2251.68 U2.20@951.05,2251.68 ; U1.13@995.67,571.73 996.06,571.34 v1(996.06,510)
  Signal w10: v1(355,543.88) 366.12,543.88 456.06,453.94 456.06,215 541.06,130 1046.06,130 1091.06,175 1091.06,410 996.06,505 v1(996.06,510)
  Bottom Layer w10: J1.73@283.43,543.88 v1(355,543.88) 458.88,543.88 500,585 500,1735 335,1900 v1(335,2249.6)
RESET: C17.1 J2.73 R7.1 S1.1 U1.31 | length 1199.4
  Top Layer w10: U1.31@1350,571.73 1350,506.06 1426.06,430 1646.51,430 R7.1@1678.51,398 C17.1@1744.61,398 1839.02,303.6 1839.02,270 1844.02,275 1885,275 2155,545 v1(2185,545)
  Bottom Layer w10: v1(2185,545) 2186.12,543.88 J2.73@2251.93,543.88
SDR_CKE: R6.1 R10.1 U2.37 | length 166.3
  Top Layer w10: U2.37@1414.05,2314.67 1505.22,2314.67 R10.1@1514.55,2324 ; R10.1@1515.55,2325 R10.1@1514.55,2324 ; R10.1@1517.54,2324 R10.1@1514.55,2324 ; R10.1@1517.72,2314.67 1517.72,2266.83 R6.1@1524.55,2260
VBAT_IN: C12.1 J1.68 U1.6 | length 1027.1
  Top Layer w10: v1(179.43,638.37) 276.63,638.37 300,615 375,615 385,625 425,625 646.61,403.39 C12.1@646.61,395 676.61,365 766.06,365 857.87,456.81 U1.6@857.87,571.73
  Bottom Layer w10: J1.68@110.2,638.37 v1(179.43,638.37)
pads on no net: H1.1 H2.1 H3.1 H4.1 J1.81 J1.82 J2.81 J2.82 U2.21 U2.35 U2.36 U2.40
copper on no net: | length 2473.7
  Top Layer w11.81: 363.69,3039.87 ccw(c314.48,3039.87) 363.69,3039.87 ; 368.69,-137.8 ccw(c319.48,-137.8) 368.69,-137.8 ; 2094.21,3080 ccw(c2045,3080) 2094.21,3080 ; 2114.21,-110 ccw(c2065,-110) 2114.21,-110
  Bottom Layer w11.81: 363.3,3040.27 ccw(c314.08,3040.27) 363.3,3040.27 ; 368.3,-137.4 ccw(c319.08,-137.4) 368.3,-137.4 ; 2094.61,3079.61 ccw(c2045.39,3079.61) 2094.61,3079.61 ; 2114.61,-110.39 ccw(c2065.39,-110.39) 2114.61,-110.39

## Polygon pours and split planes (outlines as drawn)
GND on GND "Top Overlay-No Net" (solid, remove dead copper, pour order 15): 85,2930 20,2865 20,2855 20,2730 20,475 20,90 90,20 130,20 2270,20 2340,90 2340,170 2340,2860 2270,2930
GND on Signal "Top Overlay-No Net" (solid, remove dead copper, pour order 18): 85,2930 20,2865 20,90 90,20 2270,20 2340,90 2340,2860 2270,2930
GND on Top Layer "Top Overlay-No Net" (solid, remove dead copper, pour order 21): 535.81,514.19 524.19,514.19 500,490 456.06,446.06 456.06,365 456.06,163.94 490,130 855,130 1855,130 1920,195 1920,400 1850,470 1815,505 1785,505 1815,505 1805,515 1800,515 536.61,515 535.81,514.19
GND on Bottom Layer "B1" (solid, remove dead copper, pour order 24): 85,2930 20,2865 20,90 90,20 2270,20 2340,90 2340,2860 2270,2930

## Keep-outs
Keep-Out Layer:
  circle w7.87: c122.63,-98.43 r39.37
  circle w7.87: c117.63,3079.24 r39.37
  circle w7.87: c2241.85,3040.63 r39.37
  circle w7.87: c2261.85,-149.37 r39.37
  lines w7.87: 0,2950 0,3167.67 2360,3167.67 2360,2949.97 0.03,2949.97 ; 0,-217.67 0,0 2360,0 2360,-217.67 ; 0,-217.67 967.18,-217.67 ; 0,-217.67 967.18,-217.67 ; 967.18,-217.67 1176.35,-217.67 ; 1176.35,-217.67 2360,-217.67 ; 1176.35,-217.67 2360,-217.67
  lines w10: 100.03,2949.94 2260.03,2949.94 ; 100.03,2949.97 2260.03,2949.97 ; 130,0 0,0 100,0 ; 2270,0 100,0 ; 100,0 cw(c100,100) 0,100 0,2850 cw(c100,2850) 100,2950 2260,2950 cw(c2260,2850) 2360,2850 ; 100,0 2260,0 ; 100,0 2260,0 ; 2260,0 ccw(c2260,100) 2360,100 ; 2360,100 2360,2850 ; 2360,100 2360,2850

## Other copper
Bottom Layer:
  rectangle net +3V3: 2031.06,385 2301.06,455

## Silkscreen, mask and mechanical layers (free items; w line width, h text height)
Top Overlay:
  drawing of 4272 lines, arcs and shapes, not listed
  text "APM32F407IG Core V1" at 725,1765 h98.43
